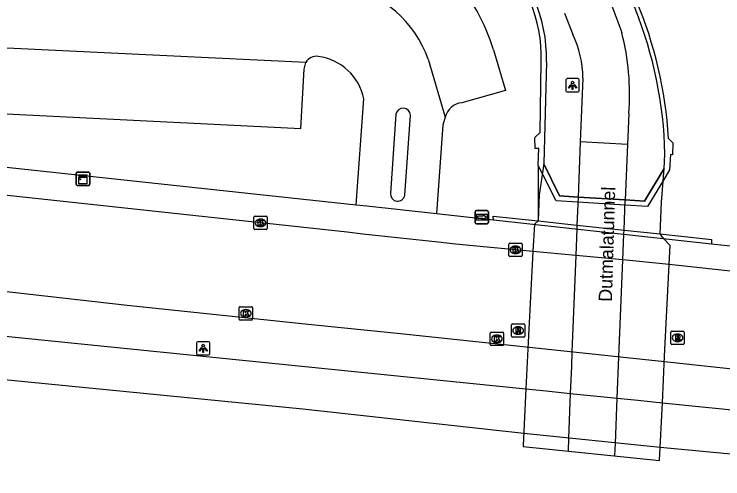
# Model space of a CAD drawing. Extents: x 161761 to 162722, y 384793 to 385405.
# Drawn here: x 162147.6 to 162200.7, y 384835 to 384869.8 of the extents above; entities that cross this region are included whole.
import ezdxf

# ---------------------------------------------------------------- set-up
doc = ezdxf.new("R2010")
doc.units = 0
for name, color, linetype in [('IMGEO_Fietspad_gesloten', 7, 'Continuous'), ('IMGEO_Groenvoorziening', 7, 'Continuous'), ('IMGEO_Kast', 7, 'Continuous'), ('IMGEO_Kolk', 7, 'Continuous'), ('IMGEO_Lichtpunt', 7, 'Continuous'), ('IMGEO_Lijnafwatering', 7, 'Continuous'), ('IMGEO_Muur', 7, 'Continuous'), ('IMGEO_Openbare_ruimte_label', 7, 'Continuous'), ('IMGEO_Parkeervlak_open', 7, 'Continuous'), ('IMGEO_Rijbaan_lokaal_open', 7, 'Continuous'), ('IMGEO_Rijbaan_regionaal_gesloten', 7, 'Continuous'), ('IMGEO_Rioolput', 7, 'Continuous'), ('IMGEO_Tunneldeel', 7, 'Continuous'), ('IMGEO_Voetpad_open', 7, 'Continuous'), ('IMGEO_Wegwijzer', 7, 'Continuous')]:
    doc.layers.add(name, color=color, linetype=linetype)

msp = doc.modelspace()

# ---------------------------------------------------------------- linework, layer by layer
at = {"layer": 'IMGEO_Fietspad_gesloten'}
for points in [[(162192.063, 384871.289), (162193.104, 384868.481)], [(162188.819, 384869.927), (162189.449, 384868.323)], [(162190.192, 384865.061), (162190.002, 384860.294), (162189.837, 384856.147)], [(162193.628, 384862.408), (162193.534, 384860.077), (162193.367, 384855.93)], [(162189.837, 384856.147), (162189.753, 384854.046), (162189.742, 384853.757), (162189.662, 384851.764), (162189.376, 384844.558), (162189.333, 384843.472), (162189.251, 384841.435), (162189.117, 384838.051), (162189.082, 384837.166), (162189.08, 384837.113)], [(162192.592, 384836.753), (162192.594, 384836.79), (162192.63, 384837.693), (162192.767, 384841.08), (162192.892, 384844.185), (162193.185, 384851.432), (162193.264, 384853.37), (162193.276, 384853.669), (162193.367, 384855.93)]]:
    msp.add_lwpolyline(points, dxfattribs=at)
for centre, radius, start, end in [((162175.196, 384863.877), 18.49, 355.444, 14.4189), ((162182.58, 384865.043), 7.612, 0.1371, 25.5261)]:
    msp.add_arc(centre, radius, start, end, dxfattribs=at)
at = {"layer": 'IMGEO_Groenvoorziening'}
msp.add_lwpolyline([(162186.855, 384858.503), (162186.847, 384854.356)], dxfattribs=at)
at = {"layer": 'IMGEO_Kast'}
for p, q in [((162152.276, 384857.087), (162152.276, 384857.928)), ((162152.276, 384857.928), (162152.276, 384857.087)), ((162152.351, 384858.012), (162153.192, 384858.012)), ((162153.192, 384858.012), (162152.351, 384858.012)), ((162153.276, 384857.937), (162153.276, 384857.096)), ((162153.276, 384857.096), (162153.276, 384857.937)), ((162153.201, 384857.012), (162152.36, 384857.012)), ((162152.36, 384857.012), (162153.201, 384857.012))]:
    msp.add_line(p, q, dxfattribs=at)
for points in [[(162152.471, 384857.802), (162153.071, 384857.802), (162153.071, 384857.717), (162152.471, 384857.717), (162152.471, 384857.802)], [(162152.471, 384857.627), (162153.071, 384857.627), (162153.071, 384857.138), (162152.471, 384857.138), (162152.471, 384857.627)]]:
    msp.add_lwpolyline(points, dxfattribs=at)
msp.add_circle((162152.555, 384857.476), 0.0377, dxfattribs=at)
for centre, start, end in [((162152.354, 384857.934), 92.4484, 184.2845), ((162152.354, 384857.934), 92.4484, 184.2845), ((162153.198, 384857.934), 2.4484, 94.2845), ((162153.198, 384857.934), 2.4484, 94.2845), ((162152.354, 384857.09), 182.4484, 274.2845), ((162152.354, 384857.09), 182.4484, 274.2845), ((162153.198, 384857.09), 272.4484, 4.2845), ((162153.198, 384857.09), 272.4484, 4.2845)]:
    msp.add_arc(centre, 0.0779, start, end, dxfattribs=at)
at = {"layer": 'IMGEO_Kolk'}
for p, q in [((162165.639, 384854.71), (162166.491, 384854.71)), ((162165.564, 384853.784), (162165.564, 384854.636)), ((162166.052, 384854.49), (162166.077, 384854.49)), ((162166.565, 384854.636), (162166.565, 384853.784)), ((162166.491, 384853.71), (162165.639, 384853.71)), ((162166.075, 384853.93), (162166.05, 384853.93)), ((162184.649, 384851.764), (162184.649, 384852.616)), ((162184.724, 384852.69), (162185.576, 384852.69)), ((162185.65, 384852.616), (162185.65, 384851.764)), ((162185.137, 384852.47), (162185.162, 384852.47)), ((162185.576, 384851.69), (162184.724, 384851.69)), ((162185.16, 384851.91), (162185.135, 384851.91)), ((162164.47, 384847.009), (162164.47, 384847.861)), ((162164.545, 384847.935), (162165.397, 384847.935)), ((162165.471, 384847.861), (162165.471, 384847.009)), ((162164.958, 384847.715), (162164.983, 384847.715)), ((162165.397, 384846.935), (162164.545, 384846.935)), ((162164.981, 384847.155), (162164.956, 384847.155)), ((162183.261, 384845.096), (162183.261, 384845.948)), ((162183.336, 384846.022), (162184.188, 384846.022)), ((162183.749, 384845.802), (162183.774, 384845.802)), ((162184.262, 384845.948), (162184.262, 384845.096)), ((162183.772, 384845.242), (162183.747, 384845.242)), ((162184.188, 384845.022), (162183.336, 384845.022))]:
    msp.add_line(p, q, dxfattribs=at)
for points in [[(162165.639, 384854.71), (162166.491, 384854.71)], [(162165.564, 384853.784), (162165.564, 384854.636)], [(162165.885, 384854.41), (162166.008, 384854.41), (162166.008, 384854.259), (162166.138, 384854.41), (162166.302, 384854.41), (162166.156, 384854.259), (162166.309, 384854.01), (162166.157, 384854.01), (162166.072, 384854.174), (162166.008, 384854.107), (162166.008, 384854.01), (162165.885, 384854.01), (162165.885, 384854.41)], [(162166.565, 384854.636), (162166.565, 384853.784)], [(162166.491, 384853.71), (162165.639, 384853.71)], [(162184.649, 384851.764), (162184.649, 384852.616)], [(162184.724, 384852.69), (162185.576, 384852.69)], [(162185.65, 384852.616), (162185.65, 384851.764)], [(162184.97, 384852.39), (162185.093, 384852.39), (162185.093, 384852.239), (162185.223, 384852.39), (162185.387, 384852.39), (162185.241, 384852.239), (162185.394, 384851.99), (162185.242, 384851.99), (162185.157, 384852.154), (162185.093, 384852.087), (162185.093, 384851.99), (162184.97, 384851.99), (162184.97, 384852.39)], [(162185.576, 384851.69), (162184.724, 384851.69)], [(162164.47, 384847.009), (162164.47, 384847.861)], [(162164.545, 384847.935), (162165.397, 384847.935)], [(162165.471, 384847.861), (162165.471, 384847.009)], [(162164.791, 384847.635), (162164.914, 384847.635), (162164.914, 384847.484), (162165.044, 384847.635), (162165.208, 384847.635), (162165.062, 384847.484), (162165.215, 384847.235), (162165.063, 384847.235), (162164.978, 384847.399), (162164.914, 384847.332), (162164.914, 384847.235), (162164.791, 384847.235), (162164.791, 384847.635)], [(162165.397, 384846.935), (162164.545, 384846.935)], [(162183.261, 384845.096), (162183.261, 384845.948)], [(162183.336, 384846.022), (162184.188, 384846.022)], [(162183.582, 384845.722), (162183.705, 384845.722), (162183.705, 384845.571), (162183.835, 384845.722), (162183.999, 384845.722), (162183.853, 384845.571), (162184.006, 384845.322), (162183.854, 384845.322), (162183.769, 384845.486), (162183.705, 384845.419), (162183.705, 384845.322), (162183.582, 384845.322), (162183.582, 384845.722)], [(162184.262, 384845.948), (162184.262, 384845.096)], [(162184.188, 384845.022), (162183.336, 384845.022)]]:
    msp.add_lwpolyline(points, dxfattribs=at)
for centre, start, end in [((162165.641, 384854.634), 91.552, 178.448), ((162165.641, 384854.634), 91.552, 178.448), ((162166.489, 384854.634), 1.552, 88.448), ((162166.489, 384854.634), 1.552, 88.448), ((162165.641, 384853.786), 181.552, 268.448), ((162165.641, 384853.786), 181.552, 268.448), ((162166.489, 384853.786), 271.552, 358.448), ((162166.489, 384853.786), 271.552, 358.448), ((162184.726, 384852.614), 91.552, 178.448), ((162184.726, 384852.614), 91.552, 178.448), ((162185.574, 384852.614), 1.552, 88.448), ((162185.574, 384852.614), 1.552, 88.448), ((162184.726, 384851.766), 181.552, 268.448), ((162184.726, 384851.766), 181.552, 268.448), ((162185.574, 384851.766), 271.552, 358.448), ((162185.574, 384851.766), 271.552, 358.448), ((162164.547, 384847.859), 91.552, 178.448), ((162164.547, 384847.859), 91.552, 178.448), ((162165.395, 384847.859), 1.552, 88.448), ((162165.395, 384847.859), 1.552, 88.448), ((162164.547, 384847.011), 181.552, 268.448), ((162164.547, 384847.011), 181.552, 268.448), ((162165.395, 384847.011), 271.552, 358.448), ((162165.395, 384847.011), 271.552, 358.448), ((162183.338, 384845.946), 91.552, 178.448), ((162183.338, 384845.946), 91.552, 178.448), ((162184.186, 384845.946), 1.552, 88.448), ((162184.186, 384845.946), 1.552, 88.448), ((162183.338, 384845.098), 181.552, 268.448), ((162183.338, 384845.098), 181.552, 268.448), ((162184.186, 384845.098), 271.552, 358.448), ((162184.186, 384845.098), 271.552, 358.448)]:
    msp.add_arc(centre, 0.0765, start, end, dxfattribs=at)
for centre, major_axis, ratio, start_param, end_param in [((162166.051, 384854.21), (-0.387, 0.002), 0.722429, 4.712389, 7.853982), ((162166.076, 384854.21), (-0.39, 0.002), 0.717154, 1.570796, 4.712389), ((162185.136, 384852.19), (-0.387, 0.002), 0.722429, 4.712389, 7.853982), ((162185.161, 384852.19), (-0.39, 0.002), 0.717154, 1.570796, 4.712389), ((162164.957, 384847.435), (-0.387, 0.002), 0.722429, 4.712389, 7.853982), ((162164.982, 384847.435), (-0.39, 0.002), 0.717154, 1.570796, 4.712389), ((162183.748, 384845.522), (-0.387, 0.002), 0.722429, 4.712389, 7.853982), ((162183.773, 384845.522), (-0.39, 0.002), 0.717154, 1.570796, 4.712389)]:
    msp.add_ellipse(centre, major_axis=major_axis, ratio=ratio, start_param=start_param, end_param=end_param, dxfattribs=at)
at = {"layer": 'IMGEO_Lichtpunt'}
for p, q in [((162188.926, 384864.922), (162188.926, 384864.115)), ((162188.926, 384864.922), (162188.926, 384864.115)), ((162189.828, 384865.017), (162189.02, 384865.017)), ((162189.828, 384865.017), (162189.02, 384865.017)), ((162189.922, 384864.115), (162189.922, 384864.922)), ((162189.922, 384864.115), (162189.922, 384864.922)), ((162189.02, 384864.021), (162189.828, 384864.021)), ((162189.02, 384864.021), (162189.828, 384864.021)), ((162161.277, 384845.218), (162161.277, 384844.411)), ((162161.277, 384845.218), (162161.277, 384844.411)), ((162162.179, 384845.313), (162161.371, 384845.313)), ((162162.179, 384845.313), (162161.371, 384845.313)), ((162162.273, 384844.411), (162162.273, 384845.218)), ((162162.273, 384844.411), (162162.273, 384845.218)), ((162161.371, 384844.317), (162162.179, 384844.317)), ((162161.371, 384844.317), (162162.179, 384844.317))]:
    msp.add_line(p, q, dxfattribs=at)
for points in [[(162189.3, 384864.586), (162189.339, 384864.558), (162189.151, 384864.296), (162189.113, 384864.323), (162189.3, 384864.586)], [(162189.402, 384864.538), (162189.449, 384864.538), (162189.449, 384864.216), (162189.402, 384864.216), (162189.402, 384864.538)], [(162189.512, 384864.558), (162189.55, 384864.585), (162189.737, 384864.323), (162189.698, 384864.295), (162189.512, 384864.558)], [(162161.651, 384844.882), (162161.69, 384844.854), (162161.502, 384844.592), (162161.464, 384844.619), (162161.651, 384844.882)], [(162161.753, 384844.834), (162161.8, 384844.834), (162161.8, 384844.512), (162161.753, 384844.512), (162161.753, 384844.834)], [(162161.863, 384844.854), (162161.901, 384844.881), (162162.088, 384844.619), (162162.049, 384844.591), (162161.863, 384844.854)]]:
    msp.add_lwpolyline(points, dxfattribs=at)
for centre in [(162189.425, 384864.72), (162161.776, 384845.016)]:
    msp.add_circle(centre, 0.0994, dxfattribs=at)
for centre, start, end in [((162189.02, 384864.922), 90, 180), ((162189.02, 384864.922), 90, 180), ((162189.828, 384864.922), 0, 90), ((162189.828, 384864.922), 0, 90), ((162189.02, 384864.115), 180, 270), ((162189.02, 384864.115), 180, 270), ((162189.828, 384864.115), 270, 0), ((162189.828, 384864.115), 270, 360), ((162161.371, 384845.218), 90, 180), ((162161.371, 384845.218), 90, 180), ((162162.179, 384845.218), 0, 90), ((162162.179, 384845.218), 0, 90), ((162161.371, 384844.411), 180, 270), ((162161.371, 384844.411), 180, 270), ((162162.179, 384844.411), 270, 0), ((162162.179, 384844.411), 270, 360)]:
    msp.add_arc(centre, 0.0946, start, end, dxfattribs=at)
at = {"layer": 'IMGEO_Lijnafwatering'}
msp.add_lwpolyline([(162193.534, 384860.077), (162190.002, 384860.294)], dxfattribs=at)
at = {"layer": 'IMGEO_Muur'}
for points in [[(162186.855, 384858.503), (162186.898, 384859.792), (162186.615, 384859.796), (162186.599, 384860.61), (162186.993, 384860.985), (162187.061, 384866.296)], [(162187.47, 384866.28), (162187.261, 384858.627), (162188.44, 384856.232), (162189.837, 384856.147)], [(162196.6, 384860.533), (162196.937, 384860.205), (162196.904, 384859.319), (162196.752, 384859.336), (162196.689, 384858.194), (162196.216, 384857.409), (162195.035, 384855.447), (162193.351, 384855.548), (162189.821, 384855.76), (162188.192, 384855.858), (162187.219, 384857.784), (162186.855, 384858.503)], [(162193.367, 384855.93), (162194.814, 384855.842), (162196.267, 384858.28), (162196.336, 384859.368)], [(162189.837, 384856.147), (162193.367, 384855.93)], [(162183.494, 384854.443), (162183.489, 384854.714), (162186.847, 384854.356)], [(162183.494, 384854.443), (162199.818, 384852.651)], [(162186.847, 384854.356), (162189.753, 384854.046), (162193.276, 384853.669), (162195.982, 384853.38), (162199.813, 384852.971), (162199.818, 384852.651)]]:
    msp.add_lwpolyline(points, dxfattribs=at)
for centre, radius, start, end in [((162165.352, 384858.704), 30.991, 1.2276, 42.6393), ((162165.318, 384858.707), 31.336, 3.3404, 42.4179), ((162176.242, 384866.536), 11.23, 358.6916, 48.704), ((162176.458, 384866.728), 10.611, 357.6657, 47.6781)]:
    msp.add_arc(centre, radius, start, end, dxfattribs=at)
at = {"layer": 'IMGEO_Parkeervlak_open'}
for points in [[(162126.643, 384867.22), (162126.477, 384863.404), (162169.081, 384861.271), (162169.319, 384865.732), (162169.465, 384866.228)], [(162183.499, 384867.187), (162184.406, 384864.142), (162181.14, 384863.206)]]:
    msp.add_lwpolyline(points, dxfattribs=at)
for centre, radius, start, end in [((162169.43, 384862.94), 14.696, 16.7976, 41.2562), ((162181.262, 384861.791), 1.421, 94.9262, 166.4261)]:
    msp.add_arc(centre, radius, start, end, dxfattribs=at)
at = {"layer": 'IMGEO_Rijbaan_lokaal_open'}
for points in [[(162169.465, 384866.228), (162125.729, 384868.331)], [(162178.605, 384866.47), (162179.881, 384862.124)], [(162173.216, 384855.57), (162173.808, 384863.498)], [(162176.204, 384862.352), (162175.781, 384856.416)], [(162176.859, 384856.295), (162177.286, 384862.277)], [(162179.881, 384862.124), (162179.701, 384861.534), (162179.23, 384854.927)], [(162248.91, 384845.406), (162196.657, 384851.104), (162193.185, 384851.432), (162189.662, 384851.764), (162186.438, 384852.069), (162180.669, 384852.613), (162179.371, 384852.762), (162173.734, 384853.372), (162172.558, 384853.51), (162145.258, 384856.454), (162132.687, 384857.788)], [(162173.216, 384855.57), (162174.012, 384855.484), (162179.23, 384854.927)], [(162121.361, 384851.862), (162140.223, 384849.851), (162156.076, 384848.057), (162169.888, 384846.605), (162176.537, 384845.917), (162196.294, 384843.825), (162204.623, 384842.922), (162216.103, 384841.703), (162220.098, 384841.298), (162225.879, 384840.718), (162233.995, 384839.83), (162238.742, 384839.348), (162246.186, 384838.478), (162253.954, 384837.702), (162266.874, 384836.344)]]:
    msp.add_lwpolyline(points, dxfattribs=at)
for centre, radius, start, end in [((162170.731, 384863.778), 8.321, 18.8745, 79.3505), ((162170.239, 384865.826), 0.872, 80.888, 152.5433), ((162169.834, 384862.663), 4.06, 11.8678, 82.3194), ((162176.742, 384862.269), 0.544, 0.8305, 171.2391), ((162176.323, 384856.378), 0.543, 176.0035, 351.1878)]:
    msp.add_arc(centre, radius, start, end, dxfattribs=at)
at = {"layer": 'IMGEO_Rijbaan_regionaal_gesloten'}
for points in [[(162214.263, 384835.667), (162195.974, 384837.38), (162185.764, 384838.425), (162169.223, 384840.267), (162133.931, 384843.718), (162120.626, 384845.08), (162091.94, 384848.018), (162044.901, 384852.969), (162005.209, 384856.921), (161970.016, 384860.621), (161942.922, 384863.321), (161930.324, 384864.521), (161916.527, 384865.621), (161905.679, 384866.421), (161890.432, 384867.121), (161871.886, 384867.92), (161845.341, 384869.071), (161828.532, 384869.772), (161828.527, 384869.772)], [(162121.052, 384848.339), (162185.929, 384841.772), (162187.436, 384841.619), (162189.251, 384841.435), (162192.767, 384841.08), (162194.3, 384840.925), (162196.141, 384840.739), (162261.713, 384834.101), (162291.726, 384830.473), (162298.135, 384829.505), (162306.89, 384828.091), (162315.827, 384826.441), (162321.473, 384825.346), (162350.99, 384818.894), (162380.078, 384810.862), (162402.695, 384803.51)]]:
    msp.add_lwpolyline(points, dxfattribs=at)
at = {"layer": 'IMGEO_Rioolput'}
for p, q in [((162184.848, 384845.718), (162184.848, 384846.57)), ((162184.923, 384846.644), (162185.775, 384846.644)), ((162185.336, 384846.424), (162185.361, 384846.424)), ((162185.849, 384846.57), (162185.849, 384845.718)), ((162185.359, 384845.864), (162185.334, 384845.864)), ((162196.778, 384845.179), (162196.778, 384846.031)), ((162196.853, 384846.105), (162197.705, 384846.105)), ((162197.266, 384845.885), (162197.291, 384845.885)), ((162197.779, 384846.031), (162197.779, 384845.179)), ((162185.775, 384845.644), (162184.923, 384845.644)), ((162197.289, 384845.325), (162197.264, 384845.325)), ((162197.705, 384845.105), (162196.853, 384845.105))]:
    msp.add_line(p, q, dxfattribs=at)
for points in [[(162184.848, 384845.718), (162184.848, 384846.57)], [(162184.923, 384846.644), (162185.775, 384846.644)], [(162185.437, 384846.342), (162185.185, 384846.344), (162185.185, 384845.944)], [(162185.363, 384846.263), (162185.309, 384846.263), (162185.309, 384846.182)], [(162185.849, 384846.57), (162185.849, 384845.718)], [(162185.185, 384845.944), (162185.309, 384845.944), (162185.309, 384846.106), (162185.32, 384846.106)], [(162185.309, 384846.182), (162185.361, 384846.182)], [(162185.367, 384846.077), (162185.438, 384845.944), (162185.578, 384845.944), (162185.513, 384846.07)], [(162196.778, 384845.179), (162196.778, 384846.031)], [(162196.853, 384846.105), (162197.705, 384846.105)], [(162197.367, 384845.803), (162197.115, 384845.805), (162197.115, 384845.405)], [(162197.293, 384845.724), (162197.239, 384845.724), (162197.239, 384845.643)], [(162197.779, 384846.031), (162197.779, 384845.179)], [(162185.775, 384845.644), (162184.923, 384845.644)], [(162197.115, 384845.405), (162197.239, 384845.405), (162197.239, 384845.567), (162197.25, 384845.567)], [(162197.239, 384845.643), (162197.291, 384845.643)], [(162197.297, 384845.538), (162197.368, 384845.405), (162197.508, 384845.405), (162197.443, 384845.531)], [(162197.705, 384845.105), (162196.853, 384845.105)]]:
    msp.add_lwpolyline(points, dxfattribs=at)
for centre, radius, start, end in [((162184.925, 384846.568), 0.0765, 91.552, 178.448), ((162184.925, 384846.568), 0.0765, 91.552, 178.448), ((162185.369, 384846.167), 0.0964, 77.0061, 93.1865), ((162185.383, 384846.224), 0.0378, 276.6634, 79.6772), ((162185.436, 384846.232), 0.109, 350.3612, 89.416), ((162185.434, 384846.232), 0.112, 277.5842, 350.9817), ((162185.773, 384846.568), 0.0765, 1.552, 88.448), ((162185.773, 384846.568), 0.0765, 1.552, 88.448), ((162184.925, 384845.72), 0.0765, 181.552, 268.448), ((162184.925, 384845.72), 0.0765, 181.552, 268.448), ((162185.319, 384846.053), 0.0533, 26.0293, 88.6989), ((162185.345, 384846.371), 0.19, 274.7715, 282.9687), ((162185.418, 384846.017), 0.108, 29.5134, 73.7905), ((162185.773, 384845.72), 0.0765, 271.552, 358.448), ((162185.773, 384845.72), 0.0765, 271.552, 358.448), ((162196.855, 384846.029), 0.0765, 91.552, 178.448), ((162196.855, 384846.029), 0.0765, 91.552, 178.448), ((162197.299, 384845.628), 0.0964, 77.0061, 93.1865), ((162197.313, 384845.685), 0.0378, 276.6634, 79.6772), ((162197.366, 384845.693), 0.109, 350.3612, 89.416), ((162197.364, 384845.693), 0.112, 277.5842, 350.9817), ((162197.703, 384846.029), 0.0765, 1.552, 88.448), ((162197.703, 384846.029), 0.0765, 1.552, 88.448), ((162196.855, 384845.181), 0.0765, 181.552, 268.448), ((162196.855, 384845.181), 0.0765, 181.552, 268.448), ((162197.249, 384845.514), 0.0533, 26.0293, 88.6989), ((162197.275, 384845.832), 0.19, 274.7715, 282.9687), ((162197.348, 384845.478), 0.108, 29.5134, 73.7905), ((162197.703, 384845.181), 0.0765, 271.552, 358.448), ((162197.703, 384845.181), 0.0765, 271.552, 358.448)]:
    msp.add_arc(centre, radius, start, end, dxfattribs=at)
for centre, major_axis, ratio, start_param, end_param in [((162185.335, 384846.144), (-0.387, 0.002), 0.722429, 4.712389, 7.853982), ((162185.36, 384846.144), (-0.39, 0.002), 0.717154, 1.570796, 4.712389), ((162197.265, 384845.605), (-0.387, 0.002), 0.722429, 4.712389, 7.853982), ((162197.29, 384845.605), (-0.39, 0.002), 0.717154, 1.570796, 4.712389)]:
    msp.add_ellipse(centre, major_axis=major_axis, ratio=ratio, start_param=start_param, end_param=end_param, dxfattribs=at)
at = {"layer": 'IMGEO_Tunneldeel'}
msp.add_lwpolyline([(162195.926, 384836.411), (162195.927, 384836.433), (162196.141, 384840.739), (162196.314, 384844.227), (162196.657, 384851.104), (162196.725, 384852.521), (162196.225, 384853.045), (162195.982, 384853.38), (162196.077, 384855.765), (162196.267, 384858.28), (162194.814, 384855.842), (162193.367, 384855.93), (162189.837, 384856.147), (162188.44, 384856.232), (162187.261, 384858.627), (162186.926, 384856.324), (162186.847, 384854.356), (162186.581, 384854.104), (162186.438, 384852.069), (162186.103, 384845.281), (162185.929, 384841.772), (162185.719, 384837.526), (162185.716, 384837.457)], close=True, dxfattribs=at)
at = {"layer": 'IMGEO_Voetpad_open'}
for points in [[(162131.027, 384860.111), (162173.216, 384855.57)], [(162179.23, 384854.927), (162183.494, 384854.443)], [(162199.818, 384852.651), (162250.191, 384847.307)]]:
    msp.add_lwpolyline(points, dxfattribs=at)
at = {"layer": 'IMGEO_Wegwijzer'}
for p, q in [((162182.128, 384854.239), (162182.128, 384855.039)), ((162182.128, 384855.039), (162182.128, 384854.239)), ((162182.228, 384855.139), (162183.018, 384855.139)), ((162183.018, 384855.139), (162182.228, 384855.139)), ((162183.118, 384855.039), (162183.118, 384854.239)), ((162183.118, 384854.239), (162183.118, 384855.039)), ((162183.018, 384854.139), (162182.228, 384854.139)), ((162182.228, 384854.139), (162183.018, 384854.139))]:
    msp.add_line(p, q, dxfattribs=at)
for points in [[(162182.229, 384854.871), (162183.017, 384854.871), (162183.017, 384854.407), (162182.229, 384854.407), (162182.229, 384854.871)], [(162182.294, 384854.723), (162182.294, 384854.639), (162182.294, 384854.555), (162182.705, 384854.555), (162182.705, 384854.472), (162182.952, 384854.639), (162182.705, 384854.806), (162182.705, 384854.723), (162182.294, 384854.723)]]:
    msp.add_lwpolyline(points, dxfattribs=at)
for centre, start, end in [((162182.228, 384855.039), 90, 180), ((162182.228, 384855.039), 90, 180), ((162183.018, 384855.039), 0, 90), ((162183.018, 384855.039), 360, 90), ((162182.228, 384854.239), 180, 270), ((162182.228, 384854.239), 180, 270), ((162183.018, 384854.239), 270, 0), ((162183.018, 384854.239), 270, 0)]:
    msp.add_arc(centre, 0.1, start, end, dxfattribs=at)

# ---------------------------------------------------------------- texts
at = {"layer": 'IMGEO_Openbare_ruimte_label'}
msp.add_text('Dutmalatunnel', height=1, rotation=88.3389, dxfattribs=at).set_placement((162192.367, 384848.29))

doc.saveas('drawing.dxf')
